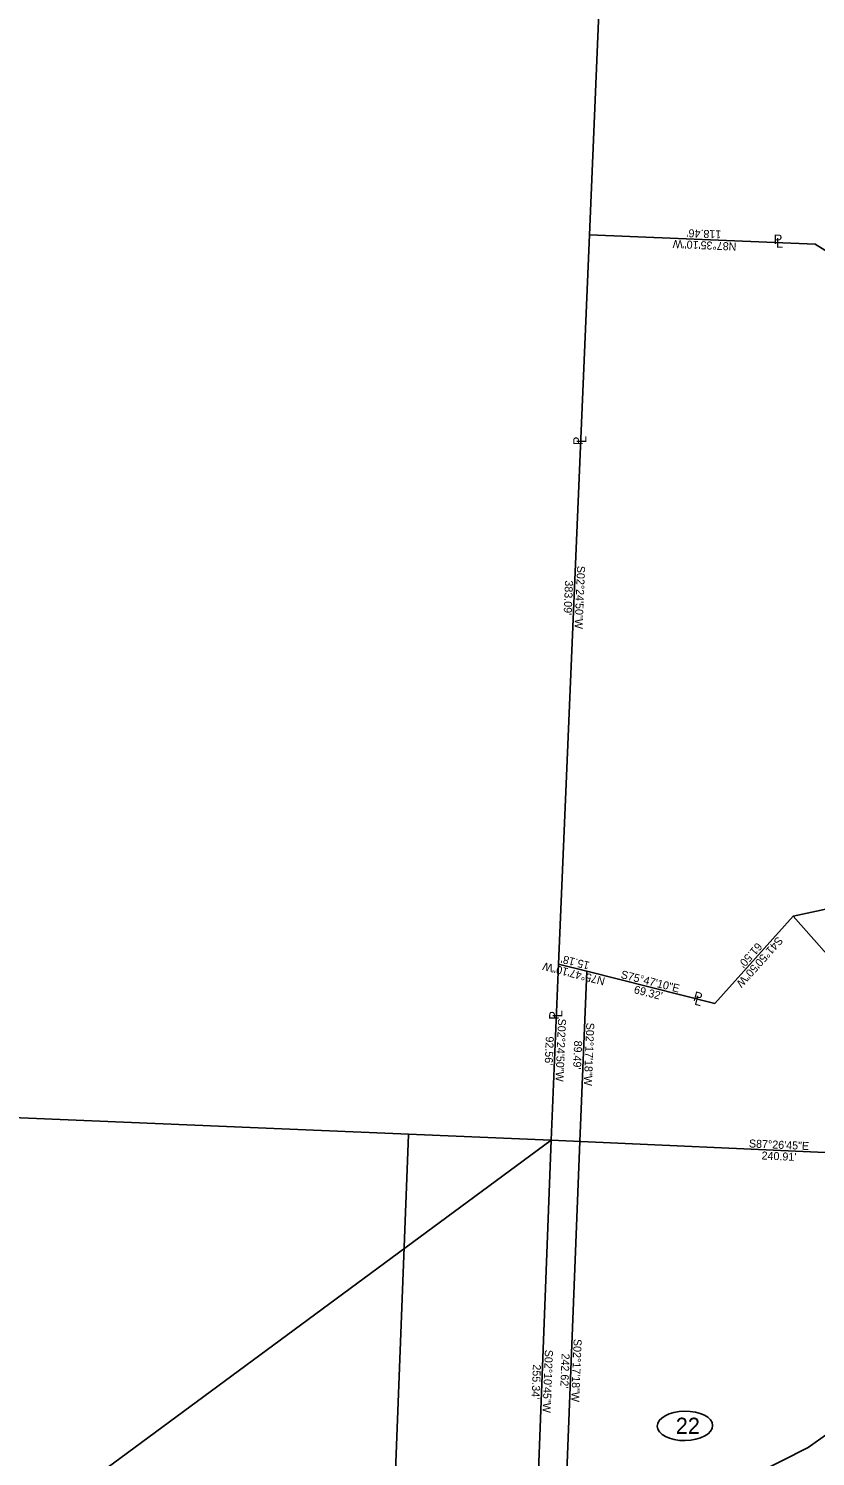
# Model space of a CAD drawing. Extents: x 1145508 to 2262867, y -3126236 to 2021677.
# Drawn here: x 1148734 to 1149147, y 2018793 to 2019543 of the extents above; entities that cross this region are included whole.
import ezdxf

# ---------------------------------------------------------------- set-up
doc = ezdxf.new("R2010")
doc.units = 0
for name, color, linetype in [('DSN_ROW_Annotation', 7, 'Continuous'), ('DSN_ROW_Line', 7, 'Continuous'), ('DSN_ROW_Line-Annotation', 7, 'Continuous'), ('DSN_ROW_Prop-Line', 7, 'Continuous'), ('DSN_ROW_Prop-Line-Annotation', 7, 'Continuous'), ('EX_QSECTION', 7, 'Continuous'), ('EX_ROW_ANNOT', 7, 'Continuous')]:
    doc.layers.add(name, color=color, linetype=linetype)

msp = doc.modelspace()

# ---------------------------------------------------------------- linework, layer by layer
at = {"layer": 'DSN_ROW_Line'}
for p, q in [((1149143.19, 2018798.06), (1149289.59, 2018902.98)), ((1149069.97, 2018761.14), (1149143.19, 2018798.06))]:
    msp.add_line(p, q, dxfattribs=at)
at = {"layer": 'DSN_ROW_Line-Annotation'}
msp.add_ellipse((1149078.6, 2018809.43), major_axis=(14.54, 0.23), ratio=0.529773, dxfattribs=at)
at = {"layer": 'DSN_ROW_Prop-Line'}
for p, q in [((1149146.87, 2019429.52), (1149028.51, 2019434.51)), ((1149361.07, 2019298.1), (1149146.87, 2019429.52)), ((1149272.1, 2019106.7), (1149135.32, 2019076.83)), ((1149135.32, 2019076.83), (1149094.29, 2019031.01)), ((1149249.15, 2018948.55), (1149135.32, 2019076.83)), ((1149027.09, 2019048.04), (1149012.38, 2019051.76)), ((1149027.09, 2019048.04), (1149023.52, 2018958.62)), ((1149027.09, 2019048.04), (1149094.29, 2019031.01)), ((1148375.95, 2018492.82), (1149008.48, 2018959.29)), ((1148933.53, 2018962.14), (1148914.48, 2018461.44)), ((1149023.52, 2018958.62), (1149013.83, 2018716.19))]:
    msp.add_line(p, q, dxfattribs=at)
at = {"layer": 'EX_QSECTION'}
for p, q in [((1149045.91, 2019847.17), (1149028.51, 2019434.51)), ((1149028.51, 2019434.51), (1149012.38, 2019051.76)), ((1149012.38, 2019051.76), (1149008.48, 2018959.29)), ((1147676.48, 2019015.88), (1149008.48, 2018959.29)), ((1149008.48, 2018959.29), (1148998.77, 2018704.13)), ((1149008.48, 2018959.29), (1149249.15, 2018948.55))]:
    msp.add_line(p, q, dxfattribs=at)

# ---------------------------------------------------------------- texts
at = {"layer": 'DSN_ROW_Annotation'}
for s, rotation, p in [('N87°35\'10"W', 177.58619, (1149105.7, 2019430.36)), ("118.46'", 177.58619, (1149097.76, 2019436.7)), ('S41°50\'50"W', 228.15286, (1149127.33, 2019066.56)), ("15.18'", 165.78619, (1149028.89, 2019052.84)), ("61.50'", 228.15286, (1149116.45, 2019063.4)), ('N75°47\'10"W', 165.78619, (1149037.02, 2019044.59)), ('S75°47\'10"E', 345.78619, (1149044.66, 2019044.51)), ("69.32'", 345.78619, (1149051.54, 2019036.58)), ('S02°17\'18"W', 267.71174, (1149026.91, 2019021.05)), ("89.49'", 267.71174, (1149020.53, 2019011.68)), ('S02°17\'18"W', 267.71174, (1149020.28, 2018855.13)), ("242.62'", 267.71174, (1149013.97, 2018847.46))]:
    msp.add_text(s, height=4.2, rotation=rotation, dxfattribs=at).set_placement(p)
at = {"layer": 'DSN_ROW_Line-Annotation'}
msp.add_text('22', height=8.5, dxfattribs=at).set_placement((1149073.82, 2018805.22))
at = {"layer": 'DSN_ROW_Prop-Line-Annotation'}
for s, p in [('P', (1149125.22, 2019429.63)), ('L', (1149126.39, 2019427.72))]:
    msp.add_text(s, height=5, dxfattribs=at).set_placement(p)
for s, rotation, p in [('P', 90, (1149024.99, 2019324.1)), ('L', 90, (1149026.91, 2019325.26)), ('P', 344.84677, (1149082.66, 2019032.72)), ('L', 344.84677, (1149083.29, 2019030.57)), ('P', 90, (1149012.38, 2019022.64)), ('L', 90, (1149014.29, 2019023.8))]:
    msp.add_text(s, height=5, rotation=rotation, dxfattribs=at).set_placement(p)
at = {"layer": 'EX_ROW_ANNOT'}
for s, rotation, p in [('S02°24\'50"W', 267.58619, (1149022.09, 2019260.85)), ('S02°24\'50"W', 267.58619, (1149022.09, 2019260.85)), ("383.09'", 267.58619, (1149015.76, 2019253.2)), ("383.09'", 267.58619, (1149015.76, 2019253.2)), ('S02°24\'50"W', 267.58619, (1149012.08, 2019023.24)), ('S02°24\'50"W', 267.58619, (1149012.08, 2019023.24)), ("92.56'", 267.58619, (1149005.68, 2019013.88)), ("92.56'", 267.58619, (1149005.68, 2019013.88)), ('S87°26\'45"E', 357.44576, (1149112.11, 2018955.57)), ('S87°26\'45"E', 357.44576, (1149112.11, 2018955.57)), ("240.91'", 357.44576, (1149118.74, 2018949.26)), ("240.91'", 357.44576, (1149118.74, 2018949.26)), ('S02°10\'45"W', 267.82095, (1149005.2, 2018849.43)), ('S02°10\'45"W', 267.82095, (1149005.2, 2018849.43)), ("255.34'", 267.82095, (1148998.9, 2018841.75)), ("255.34'", 267.82095, (1148998.9, 2018841.75))]:
    msp.add_text(s, height=4.2, rotation=rotation, dxfattribs=at).set_placement(p)

doc.saveas('drawing.dxf')
